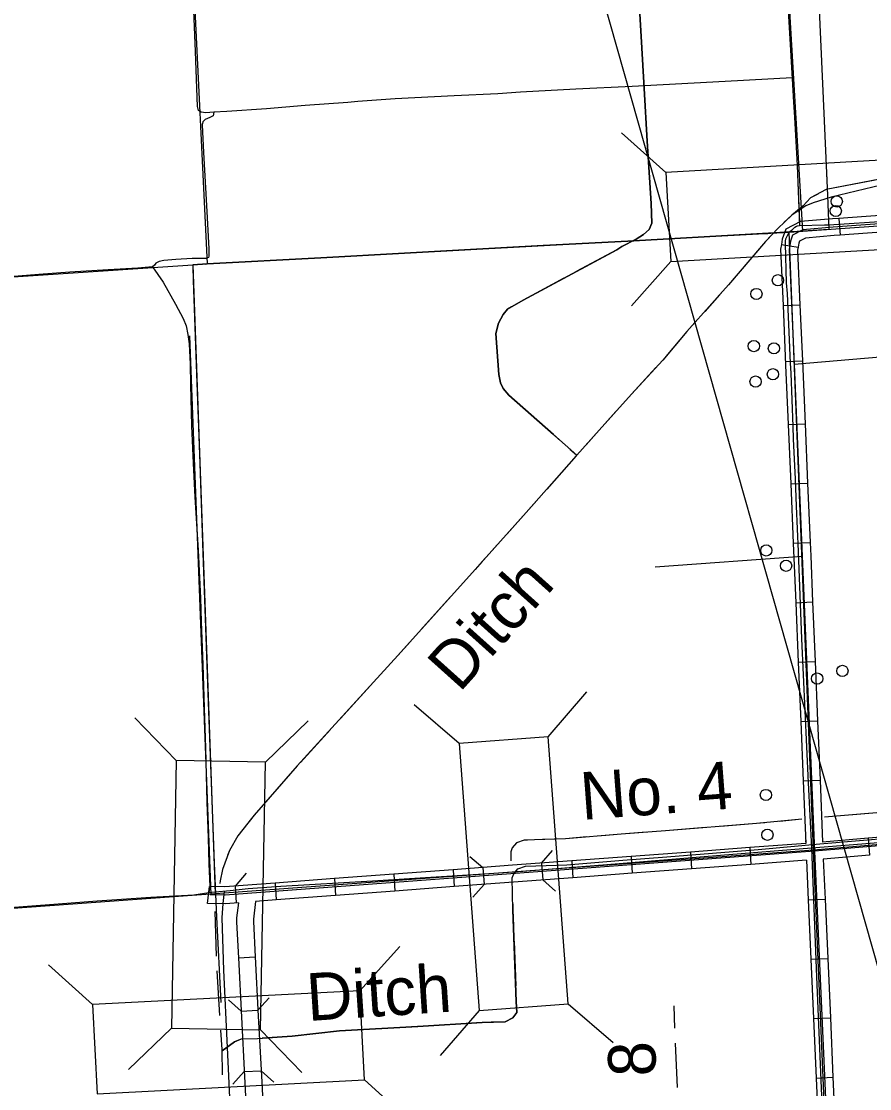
# Model space of a CAD drawing. Extents: x 646058 to 725608, y 1473014 to 1561048.
# Drawn here: x 662655 to 666420, y 1544562 to 1549300 of the extents above; entities that cross this region are included whole.
import ezdxf

# ---------------------------------------------------------------- set-up
doc = ezdxf.new("R2010")
doc.units = 0
doc.layers.add('Default', color=7, linetype='Continuous')
doc.layers.add('R_Grid', color=7, linetype='Continuous')

msp = doc.modelspace()

# ---------------------------------------------------------------- linework, layer by layer
at = {"layer": 'Default'}
for p, q in [((665515.4, 1548629), (665318.4, 1548804.8)), ((666283.2, 1548425.6), (666288.6, 1548350.8)), ((666027.8, 1548309.1), (666101.9, 1548297.7)), ((665538, 1548233.7), (665362.2, 1548036.7)), ((666035.4, 1548038.2), (666110.3, 1548041.4)), ((666045.9, 1547790.5), (666120.9, 1547793.7)), ((666058, 1547510.7), (666132.9, 1547513.9)), ((666069.4, 1547246.9), (666144.3, 1547250.2)), ((666080.9, 1546983.2), (666155.7, 1546986.4)), ((666091.8, 1546719.5), (666166.7, 1546722.6)), ((666102.7, 1546455.7), (666177.6, 1546458.8)), ((664992.8, 1546123.5), (665165.1, 1546323.6)), ((664597.9, 1546094), (664397.9, 1546266.3)), ((663342.2, 1546018.8), (663158.8, 1546208.8)), ((663738.1, 1546011.8), (663928, 1546195.2)), ((666113.6, 1546191.9), (666188.5, 1546195)), ((666124.4, 1545928.2), (666199.4, 1545931.2)), ((666413.4, 1545673.5), (666419.6, 1545598.8)), ((665624, 1545612.6), (665629.6, 1545537.8)), ((665887.3, 1545632.2), (665892.9, 1545557.4)), ((664963.3, 1545563.3), (664968.9, 1545488.5)), ((665097.5, 1545573.3), (665103.1, 1545498.5)), ((665360.8, 1545592.9), (665366.3, 1545518.1)), ((664307.7, 1545514.3), (664313.3, 1545439.5)), ((664571, 1545534), (664576.5, 1545459.2)), ((664702.7, 1545543.8), (664708.3, 1545469)), ((663781.2, 1545475), (663786.7, 1545400.2)), ((664044.4, 1545494.7), (664050, 1545419.9)), ((663603.5, 1545461.7), (663609, 1545387)), ((666146.9, 1545400.5), (666221.8, 1545403.8)), ((664158, 1544996.6), (664334.8, 1545192.7)), ((663618.2, 1545143.1), (663693.1, 1545147)), ((666158.6, 1545136.8), (666233.5, 1545140.1)), ((662971.6, 1544935.3), (662775.6, 1545112.1)), ((663630.5, 1544906.7), (663705.4, 1544910.6)), ((664686.4, 1544909.3), (664514.1, 1544709.3)), ((665081.3, 1544938.8), (665281.4, 1544766.6)), ((666170.3, 1544873), (666245.2, 1544876.4)), ((663321.2, 1544831), (663131.3, 1544647.7)), ((663717.2, 1544824), (663900.5, 1544634.1)), ((663644.4, 1544638), (663719.3, 1544641.8)), ((666182, 1544609.3), (666256.9, 1544612.6)), ((664178.5, 1544601.1), (664374.5, 1544424.3))]:
    msp.add_line(p, q, dxfattribs=at)
for points in [[(665974, 1554309.7), (665988.7, 1553980.9), (666006.9, 1553572.2), (666025.3, 1553160.3), (666037.4, 1552889.3), (666050.9, 1552586.8), (666062.2, 1552333.1), (666079.8, 1551939.6), (666100.9, 1551465.6), (666118, 1551082), (666129.2, 1550831.7), (666173.2, 1549845.3), (666198.1, 1549286), (666212.8, 1548957.6), (666229, 1548593.2)], [(665960.1, 1551021.7), (666075.8, 1549044.8)], [(665960.1, 1551021.7), (666075.8, 1549044.8)], [(666123, 1548368.2), (665965.9, 1551024.1)], [(666123, 1548368.2), (665965.9, 1551024.1)], [(663352, 1550847.2), (663480.2, 1548223.1)], [(666173.2, 1549845.3), (666198.1, 1549286), (666212.8, 1548957.6), (666232, 1548527.1), (666238.7, 1548376.4), (666123, 1548368.2), (665919.3, 1548356.1), (665346.1, 1548324.9), (664971.5, 1548304.4), (664595.7, 1548284), (664355.1, 1548270.8), (663984.5, 1548250.6), (663480.2, 1548223.1), (663415.7, 1548219.6), (663416.4, 1548199), (663417.6, 1548165.1), (663418.2, 1548149.4), (663434.4, 1547695.9), (663447.1, 1547337.5), (663461.3, 1546940.5), (663483.5, 1546318.1), (663510.4, 1545562.6), (663520.8, 1545323.9), (663540.2, 1544945)], [(666075.6, 1549048.7), (665778.2, 1549033.6), (665365.3, 1549011.1), (665116.3, 1548999.5), (664869.9, 1548985.3), (664769.2, 1548977.8), (664575.2, 1548969.5), (664314.6, 1548956.2), (664148.1, 1548944.5), (664104, 1548940.3), (663914.2, 1548926.2), (663742.7, 1548912), (663567, 1548900.4), (663508.7, 1548896.2), (663473.8, 1548893.7), (663453.8, 1548896.2), (663442.1, 1548904.5), (663437.1, 1548922), (663428.8, 1549166), (663416.3, 1549459.9)], [(666075.6, 1549048.7), (665778.2, 1549033.6), (665365.3, 1549011.1), (665116.3, 1548999.5), (664869.9, 1548985.3), (664769.2, 1548977.8), (664575.2, 1548969.5), (664314.6, 1548956.2), (664148.1, 1548944.5), (664104, 1548940.3), (663914.2, 1548926.2), (663742.7, 1548912), (663567, 1548900.4), (663508.7, 1548896.2), (663473.8, 1548893.7), (663453.8, 1548896.2), (663442.1, 1548904.5), (663437.1, 1548922), (663428.8, 1549166), (663416.3, 1549459.9)], [(665119.5, 1547373.7), (665016.2, 1547466.6), (664818, 1547641.2), (664793.3, 1547670.6), (664781.9, 1547695.2), (664773.4, 1547732.2), (664760.1, 1547914.3), (664772.5, 1547960.8), (664793.3, 1547998.8), (664812.3, 1548022.5), (664881.5, 1548062.3), (665297.8, 1548286.2), (665319.7, 1548300.4), (665383.2, 1548333.6), (665416.4, 1548354.5), (665441, 1548376.3), (665452.4, 1548403.8), (665449.6, 1548492), (665431.6, 1548768.1), (665418.3, 1549001.4), (665406.9, 1549207.2), (665393.6, 1549435.8)], [(665393.6, 1549435.8), (665406.9, 1549207.2), (665418.3, 1549001.4), (665431.6, 1548768.1), (665449.6, 1548492), (665452.4, 1548403.8), (665441, 1548376.3), (665416.4, 1548354.5), (665383.2, 1548333.6), (665319.7, 1548300.4), (665297.8, 1548286.2), (664881.5, 1548062.3), (664812.3, 1548022.5), (664793.3, 1547998.8), (664772.5, 1547960.8), (664760.1, 1547914.3), (664773.4, 1547732.2), (664781.9, 1547695.2), (664793.3, 1547670.6), (664818, 1547641.2), (665016.2, 1547466.6), (665119.5, 1547373.7)], [(665404.1, 1549255.2), (665406.9, 1549207.2), (665415.2, 1549057.5)], [(666075.8, 1549044.8), (666081.5, 1548941.7), (666086, 1548874.6), (666097.5, 1548660.7), (666101.1, 1548584.2), (666108.7, 1548393.2)], [(666075.8, 1549044.8), (666081.5, 1548941.7), (666086, 1548874.6), (666097.5, 1548660.7), (666101.1, 1548584.2), (666108.1, 1548408.5)], [(665418.8, 1548991.6), (665424.5, 1548892.7)], [(663508.7, 1548896.2), (663507.1, 1548881.2), (663491.2, 1548872.9), (663470.4, 1548864.6), (663460.4, 1548854.6), (663457.1, 1548840.4), (663462.9, 1548718), (663476.3, 1548483.2), (663487.1, 1548290.8), (663487.9, 1548257.5), (663485.4, 1548251.7), (663473.8, 1548246.7), (663413, 1548246.7), (663340.6, 1548243.3), (663287.3, 1548238.4), (663267.3, 1548233.4), (663252.3, 1548226.7), (663245.7, 1548217.5), (663237.3, 1548210), (663171.6, 1548204.2), (663040.9, 1548197.5), (662871, 1548186.7), (662732.8, 1548176.7), (662493.9, 1548156.7)], [(663508.7, 1548896.2), (663507.1, 1548881.2), (663491.2, 1548872.9), (663470.4, 1548864.6), (663460.4, 1548854.6), (663457.1, 1548840.4), (663462.9, 1548718), (663476.3, 1548483.2), (663487.1, 1548290.8), (663487.9, 1548257.5), (663485.4, 1548251.7), (663473.8, 1548246.7), (663413, 1548246.7), (663340.6, 1548243.3), (663287.3, 1548238.4), (663267.3, 1548233.4), (663252.3, 1548226.7), (663245.7, 1548217.5), (663237.3, 1548210), (663171.6, 1548204.2), (663040.9, 1548197.5), (662871, 1548186.7), (662732.8, 1548176.7), (662493.9, 1548156.7)], [(665424.5, 1548892.7), (665430.1, 1548793.9)], [(665434.2, 1548728), (665447.1, 1548530.5)], [(666542.2, 1548614), (666226.4, 1548553.2), (666156.7, 1548515.9), (666124.1, 1548480.7), (666074.5, 1548439.9), (666012, 1548381), (665957.9, 1548322.2), (665792.9, 1548130.6), (665608.9, 1547923.8), (665501.7, 1547796.7), (665362.3, 1547645), (665219.1, 1547484.6), (665119.5, 1547373.7), (664895.7, 1547119.4), (664730.7, 1546936.4), (664668.6, 1546867.1)], [(666544, 1548590.7), (666248.1, 1548519.5), (666169.4, 1548494.9), (666137.1, 1548481.6), (666074.5, 1548439.9), (666012, 1548381), (665957.9, 1548322.2), (665792.9, 1548130.6), (665608.9, 1547923.8), (665501.7, 1547796.7), (665362.3, 1547645), (665219.1, 1547484.6), (665119.5, 1547373.7), (664895.7, 1547119.4), (664730.7, 1546936.4), (664668.6, 1546867.1)], [(666444.2, 1548595.2), (666249.8, 1548557.8)], [(657996.7, 1547841.2), (660739.4, 1548040.9), (660846.4, 1548048), (663415.7, 1548219.6), (663480.2, 1548223.1), (666062.9, 1548363.9), (666123, 1548368.2), (668379.5, 1548528.5)], [(666189.2, 1548533.3), (666156.7, 1548515.9), (666124.1, 1548480.7), (666074.5, 1548439.9), (666038.9, 1548406.4)], [(668379.5, 1548535.8), (667328, 1548474.6), (667167.8, 1548464.7), (667102.9, 1548460.7), (667032.4, 1548447.9), (666975.3, 1548438.2), (666258.4, 1548386.2), (666123.8, 1548374.4)], [(666237.8, 1548397.5), (666508.6, 1548413.8), (666698.4, 1548430.4), (666807.3, 1548437.6), (666954.5, 1548447.7), (667015.8, 1548452.8), (667113.2, 1548466.5), (667168, 1548475.1), (667194, 1548477.3), (667338.3, 1548486), (667535.2, 1548495.4), (667924.1, 1548516.3), (668379.5, 1548541.8)], [(665450.5, 1548464.5), (665452.4, 1548403.8), (665441, 1548376.3), (665416.4, 1548354.5), (665383.2, 1548333.6), (665351.9, 1548317.3)], [(666283.2, 1548425.6), (666255.4, 1548423.5), (666113.3, 1548411.2), (666047.6, 1548378), (666031.5, 1548333.5), (666027.8, 1548309.1)], [(666546.5, 1548444.7), (666283.2, 1548425.6)], [(663415.7, 1548219.6), (663480.2, 1548223.1), (666062.9, 1548363.9), (666123, 1548368.2)], [(663472.6, 1548222.7), (663480.2, 1548223.1), (663984.5, 1548250.6), (664355.1, 1548270.8), (664971.5, 1548304.4), (665346.1, 1548324.9), (665919.3, 1548356.1), (665967.4, 1548359)], [(665992.3, 1548359.7), (665957.9, 1548322.2), (665861.9, 1548210.8)], [(666163.1, 1545630.1), (666148.9, 1545919.8), (666118.8, 1546558.5), (666103.5, 1546946.4), (666095.5, 1547148), (666090, 1547267.5), (666081.9, 1547446.8), (666080.5, 1547501.8), (666070.9, 1547738.8), (666068.9, 1547782.6), (666054.9, 1548091.8), (666051, 1548138.9), (666046, 1548314.2), (666045.9, 1548314.8), (666046.4, 1548324.8), (666048.3, 1548334.6), (666051.4, 1548344.1), (666055.8, 1548353.1), (666061.4, 1548361.4), (666063.7, 1548364)], [(666123.8, 1548374.4), (666077.8, 1548351.2), (666068.1, 1548324.2), (666062.3, 1548286.7), (666084, 1547777.4), (666120.8, 1546925.6), (666174.9, 1545616.1), (666232.3, 1544320.8), (666247.7, 1543949.1)], [(666170.4, 1545620.6), (666062.9, 1548363.9)], [(666063.6, 1548364), (666066, 1548366.7), (666073.5, 1548373.8), (666077.2, 1548376.6), (666088.1, 1548385.9), (666095.4, 1548391.2), (666099.1, 1548392.7), (666108.7, 1548393.2)], [(666108.7, 1548393.2), (666219.2, 1548396.4), (666237.8, 1548397.5)], [(666551.9, 1548369.9), (666288.6, 1548350.8)], [(666027.8, 1548309.1), (666024.7, 1548288.8), (666035.4, 1548038.2)], [(666288.6, 1548350.8), (666261.4, 1548348.8), (666134.2, 1548337.7), (666108, 1548324.5), (666104.6, 1548314.9), (666101.9, 1548297.7)], [(665294.7, 1548284.5), (665120.3, 1548190.7)], [(666101.9, 1548297.7), (666099.9, 1548284.7), (666110.3, 1548041.4)], [(663415.7, 1548219.6), (663515.5, 1545427.8)], [(663237.3, 1548210), (663285.1, 1548142.5), (663339.1, 1548044.4), (663373.2, 1547980.4), (663386.5, 1547948), (663394, 1547909.8), (663399.8, 1547868.3), (663403.9, 1547778.5), (663405.6, 1547687.1), (663410.6, 1547504.3), (663418.1, 1547338.9), (663425.5, 1547187.7), (663439.7, 1546952.6), (663450.5, 1546739), (663453, 1546634.3), (663460.4, 1546445.7), (663466.3, 1546252.9), (663472.1, 1546075.9), (663478.7, 1545834.1), (663483.7, 1545676.2), (663487.9, 1545560.7), (663491.2, 1545464.3), (663487, 1545431.9)], [(663237.3, 1548210), (663285.1, 1548142.5), (663339.1, 1548044.4), (663373.2, 1547980.4), (663386.5, 1547948), (663394, 1547909.8), (663399.8, 1547868.3), (663403.9, 1547778.5), (663405.6, 1547687.1), (663410.6, 1547504.3), (663418.1, 1547338.9), (663425.5, 1547187.7), (663439.7, 1546952.6), (663450.5, 1546739), (663453, 1546634.3), (663460.4, 1546445.7), (663466.3, 1546252.9), (663472.1, 1546075.9), (663478.7, 1545834.1), (663483.7, 1545676.2), (663487.9, 1545560.7), (663491.3, 1545459.6)], [(665062.2, 1548159.5), (664887.8, 1548065.7)], [(665818.8, 1548160.7), (665792.9, 1548130.6), (665753.5, 1548086.4)], [(665753.5, 1548086.4), (665687.7, 1548012.4)], [(664830.5, 1548032.9), (664812.3, 1548022.5), (664793.3, 1547998.8), (664772.5, 1547960.8), (664760.1, 1547914.3), (664764.1, 1547859.2)], [(666035.4, 1548038.2), (666046.6, 1547775.8), (666046.6, 1547774.4)], [(666110.3, 1548041.4), (666120.9, 1547793.7)], [(665643.8, 1547963.1), (665608.9, 1547923.8), (665515.1, 1547812.6)], [(663401.5, 1547904.6), (663496.8, 1545422)], [(664768.9, 1547793.4), (664773.4, 1547732.2), (664781.9, 1547695.5)], [(666657.5, 1547825.4), (666084, 1547777.4)], [(666120.9, 1547793.7), (666132.9, 1547513.9)], [(665471.2, 1547763.4), (665362.3, 1547645), (665337.6, 1547617.3)], [(666046.6, 1547774.4), (666058, 1547510.7)], [(664781.9, 1547695.5), (664781.9, 1547695.2), (664793.3, 1547670.6), (664818, 1547641.2), (664842.9, 1547619.3)], [(664892.4, 1547575.6), (665016.2, 1547466.6), (665040.8, 1547444.5)], [(665293.6, 1547568.1), (665219.1, 1547484.6), (665161.6, 1547420.5)], [(666058, 1547510.7), (666069.4, 1547246.9)], [(666132.9, 1547513.9), (666144.3, 1547250.2)], [(665117.5, 1547371.4), (664986.7, 1547222.8)], [(665089.8, 1547400.4), (665119.5, 1547373.7)], [(666069.4, 1547246.9), (666080.8, 1546983.2)], [(666144.3, 1547250.2), (666155.7, 1546986.4)], [(664943.1, 1547173.2), (664895.7, 1547119.4), (664811.1, 1547025.6)], [(666080.9, 1546983.2), (666091.8, 1546719.5)], [(666155.7, 1546986.4), (666158.2, 1546927.2), (666166.7, 1546722.6)], [(664767, 1546976.6), (664730.7, 1546936.4), (664700.7, 1546903)], [(664700.7, 1546903), (664668.6, 1546867.1)], [(665467.2, 1546878.5), (666120.8, 1546925.6)], [(664668.6, 1546867.1), (664326, 1546485.5), (663879, 1545994.8), (663689, 1545776.7), (663615.8, 1545684.8), (663578.4, 1545619.4), (663547.3, 1545535.3), (663537.9, 1545485.4), (663535.8, 1545473.6)], [(664668.6, 1546867.1), (664602.5, 1546793.5)], [(664558.4, 1546744.4), (664426.1, 1546597)], [(666091.8, 1546719.5), (666102.7, 1546455.7)], [(666166.7, 1546722.6), (666177.6, 1546458.8)], [(664382, 1546547.9), (664326, 1546485.5), (664249.2, 1546401.1)], [(666177.6, 1546458.8), (666188.5, 1546195)], [(666102.7, 1546455.7), (666113.6, 1546191.9)], [(664204.7, 1546352.3), (664071.4, 1546206)], [(666113.6, 1546191.9), (666124.4, 1545928.2)], [(666188.5, 1546195), (666199.4, 1545931.2)], [(664026.9, 1546157.2), (663893.6, 1546010.8)], [(663849.9, 1545961.4), (663719.8, 1545812.1)], [(666124.4, 1545928.2), (666135.9, 1545650.8)], [(666199.4, 1545931.2), (666210.7, 1545656.7)], [(667367.9, 1545865), (667268.9, 1545855.7), (666956.1, 1545829.9), (666683.7, 1545806.1), (666219.4, 1545767.2)], [(668379.5, 1545799), (666174.9, 1545616.1), (663559.9, 1545420.9), (663496.8, 1545422), (663493.1, 1545421.7)], [(668379.5, 1545816.5), (668133.3, 1545797.4), (667719.5, 1545766), (667069.4, 1545708.5), (666459.1, 1545653.1), (666161.2, 1545630.1)], [(668379.5, 1545808.8), (666170.4, 1545620.6)], [(663677.1, 1545761.8), (663615.8, 1545684.8), (663615.5, 1545684.3)], [(666118.6, 1545758), (665917.9, 1545739), (665513.3, 1545707), (665317.2, 1545691.6), (665069.5, 1545671.9), (664885.8, 1545664.7), (664851.8, 1545653.4), (664833.2, 1545631.7), (664827, 1545613.1), (664827.9, 1545574)], [(664835.9, 1544876.1), (664853.4, 1544899.8), (664851.3, 1544949.4), (664836.9, 1545356.1), (664833.8, 1545497.5), (664840, 1545516.1), (664858.6, 1545537.8), (664892.6, 1545549.2), (665076.3, 1545556.4), (665324, 1545576), (665520.1, 1545591.5), (665924.7, 1545623.5), (666198.2, 1545649.3), (666690.5, 1545690.6), (666962.9, 1545714.3), (667275.6, 1545740.1), (667374.7, 1545749.4)], [(666118.6, 1545758), (666020, 1545748.7)], [(666414.4, 1545783.6), (666219.4, 1545767.2)], [(665428, 1545700.3), (665317.2, 1545691.6), (665230.6, 1545684.7)], [(665691.2, 1545721.1), (665513.3, 1545707), (665493.8, 1545705.5)], [(665954.3, 1545742.5), (665917.9, 1545739), (665757, 1545726.3)], [(663615.5, 1545684.3), (663578.4, 1545619.4), (663570, 1545596.6)], [(664901.3, 1545665.3), (664885.8, 1545664.7), (664851.8, 1545653.4), (664833.2, 1545631.7), (664827, 1545613.1), (664827.9, 1545574)], [(665164.8, 1545679.5), (665069.5, 1545671.9), (664967.2, 1545667.9)], [(666135.3, 1545664.4), (666135.9, 1545650.8)], [(666413.4, 1545673.5), (666210.7, 1545656.7)], [(666676.5, 1545695.3), (666413.4, 1545673.5)], [(666170.4, 1545620.6), (663515.5, 1545427.8)], [(666161.2, 1545630.1), (665757.8, 1545597.7), (665235.2, 1545553.8), (664862.1, 1545524.6), (664707.4, 1545514.1), (664213.1, 1545483.8), (663806.5, 1545459.7), (663662.3, 1545449.3), (663581.8, 1545439.9), (663516, 1545434.5)], [(664963.3, 1545563.3), (665012.2, 1545620.1)], [(665624, 1545612.6), (665360.8, 1545592.9)], [(665887.3, 1545632.2), (665624, 1545612.6)], [(666135.9, 1545650.8), (665887.3, 1545632.2)], [(666216, 1544317.7), (666184.5, 1545058.4), (666163.1, 1545630.1)], [(666241.7, 1543949.1), (666170.4, 1545620.6)], [(664645.9, 1545592.7), (664702.7, 1545543.8)], [(665097.5, 1545573.3), (664834.2, 1545553.6)], [(665360.8, 1545592.9), (665097.5, 1545573.3)], [(666139.1, 1545575.8), (665892.9, 1545557.4)], [(666139.1, 1545575.8), (666146.9, 1545400.5)], [(666419.6, 1545598.8), (666213.9, 1545581.7)], [(666213.9, 1545581.7), (666221.8, 1545403.8)], [(663652.4, 1545518.6), (663603.5, 1545461.7)], [(664307.7, 1545514.3), (664044.4, 1545494.7)], [(664571, 1545534), (664307.7, 1545514.3)], [(664834.2, 1545553.6), (664571, 1545534)], [(665366.3, 1545518.1), (665103.1, 1545498.5)], [(665629.6, 1545537.8), (665366.3, 1545518.1)], [(665892.9, 1545557.4), (665629.6, 1545537.8)], [(663781.2, 1545475), (663558.9, 1545458.4), (663490.6, 1545459.6)], [(664044.4, 1545494.7), (663781.2, 1545475)], [(664839.8, 1545478.8), (664576.5, 1545459.2)], [(664708.3, 1545469), (664659.4, 1545412.2)], [(665103.1, 1545498.5), (664839.8, 1545478.8)], [(665025.7, 1545439.5), (664968.9, 1545488.5)], [(663515.5, 1545427.8), (661496.4, 1545281.1), (660860.6, 1545222)], [(663516, 1545434.5), (663487, 1545431.9), (663421.4, 1545421.1), (663230.3, 1545411.1), (662991.1, 1545394.5), (662527.5, 1545359.6), (662137.9, 1545329.7), (661841.3, 1545308.9), (661518.1, 1545284.8)], [(663487, 1545431.9), (663421.4, 1545421.1), (663230.3, 1545411.1), (662991.1, 1545394.5), (662527.5, 1545359.6), (662137.9, 1545329.7), (661841.3, 1545308.9), (661518.1, 1545284.8)], [(663618.7, 1545387.7), (663561, 1545383.4), (663481, 1545384.8), (663490.6, 1545459.6)], [(663555.8, 1545437.8), (663549.4, 1545384.5), (663544.2, 1545320.7), (663552.6, 1545088.6), (663568.2, 1544744.7), (663586, 1544364.2), (663597.5, 1544120.6)], [(664050, 1545419.9), (663786.7, 1545400.2)], [(664313.3, 1545439.5), (664050, 1545419.9)], [(664576.5, 1545459.2), (664313.3, 1545439.5)], [(663618.7, 1545387.7), (663610, 1545320), (663610, 1545302), (663618.2, 1545143.1)], [(663695, 1545393.4), (663685, 1545315.3), (663685, 1545304.1), (663693.1, 1545147)], [(663786.7, 1545400.2), (663695, 1545393.4)], [(664836.3, 1545382), (664836.9, 1545356.1), (664851.3, 1544949.4), (664853.4, 1544899.8), (664835.9, 1544876.1)], [(664836.3, 1545382), (664836.9, 1545356.1), (664839.5, 1545283.1)], [(666146.9, 1545400.5), (666158.6, 1545136.8)], [(666221.8, 1545403.8), (666233.5, 1545140.1)], [(663520.6, 1545151), (663514.8, 1545348.9)], [(664841.8, 1545217.1), (664848.9, 1545019.2)], [(663618.2, 1545143.1), (663631.9, 1544879.5)], [(663693.1, 1545147), (663706.8, 1544883.4)], [(666158.6, 1545136.8), (666170.3, 1544873)], [(666233.5, 1545140.1), (666245.2, 1544876.4)], [(663536.5, 1544887.4), (663524.4, 1545085.1)], [(663630.5, 1544906.3), (663574.8, 1544956.5)], [(663755.6, 1544965.9), (663705.4, 1544910.2)], [(664851.2, 1544953.3), (664851.3, 1544949.4), (664853.4, 1544899.8), (664835.9, 1544876.1)], [(665550.4, 1544929.5), (665554.3, 1544830.6)], [(663545.8, 1544730.6), (663601.5, 1544770.8), (663631.5, 1544783.2), (663702.7, 1544785.3), (663856.4, 1544794.6), (664067, 1544818.3), (664414.8, 1544837.9), (664700.7, 1544855.5), (664801.8, 1544859.6), (664835.9, 1544876.1)], [(663631.9, 1544879.5), (663645.5, 1544615.9)], [(663706.8, 1544883.4), (663720.4, 1544619.7)], [(664835.9, 1544876.1), (664801.8, 1544859.6), (664700.7, 1544855.5), (664414.8, 1544837.9), (664067, 1544818.3), (663856.4, 1544794.6), (663724, 1544786.5)], [(664674.8, 1544853.9), (664477.2, 1544841.7)], [(664835.9, 1544876.1), (664801.8, 1544859.6), (664740.7, 1544857.1)], [(666170.3, 1544873), (666182, 1544609.3)], [(666245.2, 1544876.4), (666256.9, 1544612.6)], [(663548.2, 1544623.7), (663545.7, 1544736.1), (663540.5, 1544821.6)], [(664147.7, 1544822.8), (664067, 1544818.3), (663950.6, 1544805.2)], [(664411.3, 1544837.7), (664213.6, 1544826.6)], [(663626.4, 1544781.1), (663601.5, 1544770.8), (663545.8, 1544730.6)], [(663626.4, 1544781.1), (663601.5, 1544770.8), (663545.8, 1544730.6)], [(663885, 1544797.8), (663856.4, 1544794.6), (663724, 1544786.5)], [(665557, 1544764.6), (665564.9, 1544566.8)], [(663594.1, 1544582.3), (663644.4, 1544638)], [(663645.5, 1544615.9), (663659.1, 1544352.2)], [(663719.3, 1544641.8), (663775, 1544591.6)], [(663720.4, 1544619.7), (663734, 1544356.1)], [(666256.9, 1544612.6), (666269.8, 1544322.4)], [(666182, 1544609.3), (666193.7, 1544345.6)]]:
    msp.add_lwpolyline(points, dxfattribs=at)
for points in [[(666701.5, 1548696.7), (665515.4, 1548629), (665538, 1548233.7), (666724, 1548301.4)], [(664597.9, 1546094), (664686.4, 1544909.3), (665081.3, 1544938.8), (664992.8, 1546123.5)], [(663717.2, 1544824), (663738.1, 1546011.8), (663342.2, 1546018.8), (663321.2, 1544831)], [(664158, 1544996.6), (662971.6, 1544935.3), (662992.1, 1544539.8), (664178.5, 1544601.1)]]:
    msp.add_lwpolyline(points, close=True, dxfattribs=at)
for centre in [(666273.4, 1548500.7), (666269.4, 1548458.2), (666012.4, 1548150.6), (665917.2, 1548089.9), (665905.7, 1547858.7), (665994.8, 1547848.5), (665990.2, 1547733.5), (665913.2, 1547701.1), (665961, 1546951.3), (666048.6, 1546883.2), (666298.6, 1546416.6), (666186.7, 1546382.6), (665959.1, 1545865.9), (665965.9, 1545689.1)]:
    msp.add_circle(centre, 25, dxfattribs=at)
at = {"layer": 'R_Grid'}
msp.add_line((667134.7, 1542708.4), (664326.9, 1552612.1), dxfattribs=at)

# ---------------------------------------------------------------- texts
at = {"layer": 'Default'}
for s, rotation, p in [('Ditch', 48.0974, (664599.4, 1546316.8)), ('No. 4', 4.3532, (665143.6, 1545754.9)), ('Ditch', 3.7671, (663927.5, 1544862.3)), ('No. 8', 91.3415, (665484, 1544100.2))]:
    msp.add_text(s, height=211.2, rotation=rotation, dxfattribs=at).set_placement(p)

doc.saveas('drawing.dxf')
